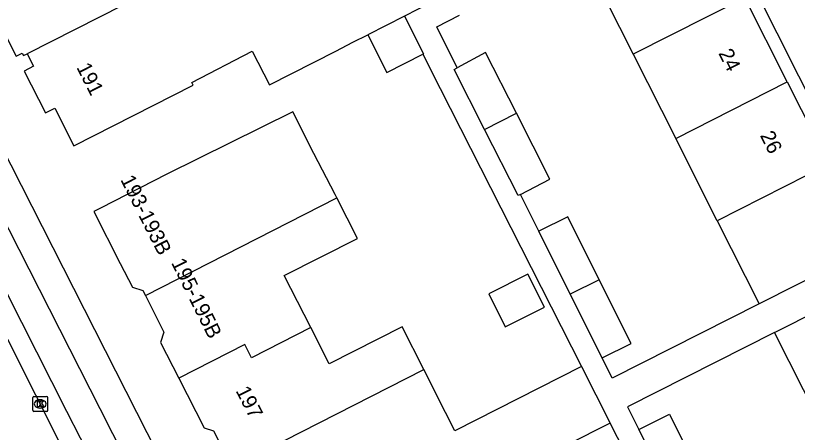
# Model space of a CAD drawing. Extents: x 162347 to 162868, y 381221 to 381813.
# Drawn here: x 162397.4 to 162450, y 381573.3 to 381601.3 of the extents above; entities that cross this region are included whole.
import ezdxf

# ---------------------------------------------------------------- set-up
doc = ezdxf.new("R2010")
doc.units = 0
for name, color, linetype in [('IMGEO_Fietspad_open', 7, 'Continuous'), ('IMGEO_Kolk', 7, 'Continuous'), ('IMGEO_Pand', 7, 'Continuous'), ('IMGEO_Pand_nummerreeks', 7, 'Continuous'), ('IMGEO_Rijbaan_regionaal_gesloten', 7, 'Continuous'), ('IMGEO_Voetpad_open', 7, 'Continuous')]:
    doc.layers.add(name, color=color, linetype=linetype)

msp = doc.modelspace()

# ---------------------------------------------------------------- linework, layer by layer
at = {"layer": 'IMGEO_Fietspad_open'}
for points in [[(162362.948, 381654.184), (162366.42, 381647.346), (162373.547, 381633.19), (162382.229, 381616.136), (162390.519, 381599.747), (162395.607, 381589.625), (162403.109, 381574.937), (162411.637, 381558.14), (162419.849, 381541.928), (162427.81, 381526.456), (162437.491, 381507.399), (162441.265, 381500), (162456.812, 381469.521), (162464.953, 381453.521)], [(162410.306, 381556.355), (162407.33, 381562.188), (162400.899, 381574.731), (162395.837, 381584.693), (162393.201, 381589.881), (162392.517, 381591.227), (162388.339, 381599.637), (162387.808, 381600.705), (162382.464, 381611.316), (162380.864, 381614.494), (162379.579, 381616.989), (162374.942, 381625.996), (162370.754, 381634.243), (162367.724, 381640.204), (162364.002, 381647.524), (162361.111, 381653.216)]]:
    msp.add_lwpolyline(points, dxfattribs=at)
at = {"layer": 'IMGEO_Kolk'}
for p, q in [((162398.602, 381574.808), (162398.602, 381575.66)), ((162398.677, 381575.734), (162399.529, 381575.734)), ((162399.09, 381575.514), (162399.115, 381575.514)), ((162399.603, 381575.66), (162399.603, 381574.808)), ((162399.113, 381574.954), (162399.088, 381574.954)), ((162399.529, 381574.734), (162398.677, 381574.734))]:
    msp.add_line(p, q, dxfattribs=at)
for points in [[(162398.602, 381574.808), (162398.602, 381575.66)], [(162398.677, 381575.734), (162399.529, 381575.734)], [(162398.923, 381575.434), (162399.046, 381575.434), (162399.046, 381575.283), (162399.176, 381575.434), (162399.34, 381575.434), (162399.194, 381575.283), (162399.347, 381575.034), (162399.195, 381575.034), (162399.11, 381575.198), (162399.046, 381575.131), (162399.046, 381575.034), (162398.923, 381575.034), (162398.923, 381575.434)], [(162399.603, 381575.66), (162399.603, 381574.808)], [(162399.529, 381574.734), (162398.677, 381574.734)]]:
    msp.add_lwpolyline(points, dxfattribs=at)
for centre, start, end in [((162398.679, 381575.658), 91.552, 178.448), ((162398.679, 381575.658), 91.552, 178.448), ((162399.527, 381575.658), 1.552, 88.448), ((162399.527, 381575.658), 1.552, 88.448), ((162398.679, 381574.81), 181.552, 268.448), ((162398.679, 381574.81), 181.552, 268.448), ((162399.527, 381574.81), 271.552, 358.448), ((162399.527, 381574.81), 271.552, 358.448)]:
    msp.add_arc(centre, 0.0765, start, end, dxfattribs=at)
for centre, major_axis, ratio, start_param, end_param in [((162399.089, 381575.234), (-0.387, 0.002), 0.722429, 4.712389, 7.853982), ((162399.114, 381575.234), (-0.39, 0.002), 0.717154, 1.570796, 4.712389)]:
    msp.add_ellipse(centre, major_axis=major_axis, ratio=ratio, start_param=start_param, end_param=end_param, dxfattribs=at)
at = {"layer": 'IMGEO_Pand'}
for points in [[(162408.169, 381603.815), (162408.091, 381603.968), (162407.93, 381604.285), (162406.673, 381606.755), (162409.231, 381608.056), (162407.798, 381610.873), (162399.497, 381606.65), (162395.04, 381604.382), (162395.432, 381603.613), (162395.031, 381603.409), (162397.484, 381598.588), (162397.885, 381598.792), (162397.971, 381598.622), (162398.225, 381598.75)], [(162421.093, 381610.584), (162425.348, 381602.17), (162423.591, 381601.277)], [(162408.169, 381603.815), (162407.903, 381603.676), (162398.225, 381598.75)], [(162436.22, 381604.184), (162438.975, 381598.725)], [(162446.477, 381602.521), (162438.975, 381598.725)], [(162449.333, 381596.861), (162446.477, 381602.521)], [(162423.591, 381601.277), (162421.123, 381600.023)], [(162423.591, 381601.277), (162424.876, 381598.735), (162424.83, 381598.712)], [(162398.225, 381598.75), (162398.654, 381597.907), (162398.031, 381597.59), (162399.459, 381594.783), (162400.082, 381595.1), (162401.374, 381592.559), (162409.395, 381596.64), (162409.305, 381596.816), (162413.361, 381598.924), (162414.513, 381596.661), (162418.97, 381598.929), (162420.127, 381599.517), (162421.123, 381600.023)], [(162421.123, 381600.023), (162422.406, 381597.486), (162424.83, 381598.712)], [(162431.122, 381594.751), (162429.049, 381598.831), (162427.136, 381597.807)], [(162438.975, 381598.725), (162441.832, 381593.065)], [(162428.983, 381593.669), (162426.937, 381597.701), (162427.136, 381597.807)], [(162441.832, 381593.065), (162449.333, 381596.861)], [(162449.333, 381596.861), (162452.128, 381591.331)], [(162419.052, 381589.067), (162418.929, 381589.309), (162417.498, 381592.056), (162416.078, 381594.848), (162407.611, 381590.658), (162403.154, 381588.39), (162402.711, 381588.165), (162404.489, 381584.67), (162405.3, 381583.076), (162406, 381582.848), (162406.171, 381582.512)], [(162428.983, 381593.669), (162431.122, 381594.751)], [(162431.389, 381589.304), (162433.37, 381590.327), (162431.122, 381594.751)], [(162431.389, 381589.304), (162431.238, 381589.226), (162428.983, 381593.669)], [(162444.624, 381587.534), (162441.832, 381593.065)], [(162452.128, 381591.331), (162444.624, 381587.534)], [(162406.171, 381582.512), (162419.052, 381589.067)], [(162417.289, 381580.365), (162415.516, 381583.85), (162420.434, 381586.352), (162419.052, 381589.067)], [(162436.693, 381583.574), (162434.575, 381587.809), (162432.624, 381586.834)], [(162444.624, 381587.534), (162447.443, 381581.948)], [(162434.744, 381582.595), (162432.624, 381586.834)], [(162454.951, 381585.737), (162447.443, 381581.948)], [(162429.261, 381582.633), (162430.371, 381580.414), (162433.002, 381581.73), (162431.892, 381583.949), (162429.261, 381582.633)], [(162448.475, 381580.031), (162451.541, 381581.582), (162456.002, 381583.84)], [(162436.693, 381583.574), (162434.744, 381582.595)], [(162436.878, 381578.326), (162438.829, 381579.302), (162436.693, 381583.574)], [(162406.171, 381582.512), (162407.423, 381580.052), (162407.199, 381579.365), (162408.417, 381576.971)], [(162436.878, 381578.326), (162434.744, 381582.595)], [(162417.289, 381580.365), (162413.312, 381578.341), (162412.859, 381579.232), (162408.417, 381576.971)], [(162424.894, 381577.551), (162423.437, 381580.415), (162418.533, 381577.92), (162417.289, 381580.365)], [(162451.409, 381574.236), (162448.475, 381580.031)], [(162412, 381570.989), (162424.894, 381577.551)], [(162435.49, 381577.756), (162426.984, 381573.427), (162426.362, 381574.649), (162424.894, 381577.551)], [(162435.49, 381577.756), (162437.424, 381573.954)], [(162408.417, 381576.971), (162410.117, 381573.63), (162410.763, 381573.42), (162412, 381570.989)], [(162439.361, 381573.514), (162441.413, 381574.54), (162443.458, 381570.449)], [(162437.424, 381573.954), (162428.846, 381569.617)], [(162440.071, 381568.694), (162439.413, 381570.046), (162437.424, 381573.954)], [(162441.411, 381569.413), (162439.361, 381573.514)]]:
    msp.add_lwpolyline(points, dxfattribs=at)
at = {"layer": 'IMGEO_Rijbaan_regionaal_gesloten'}
msp.add_lwpolyline([(162409.049, 381555.709), (162408.71, 381556.396), (162406.049, 381561.587), (162402.557, 381568.4), (162396.915, 381579.56), (162394.619, 381584.098), (162391.996, 381589.28), (162387.783, 381597.606), (162387.066, 381599.034), (162383.842, 381605.454), (162381.2, 381610.636), (162378.309, 381616.304), (162376.144, 381620.551), (162370.915, 381630.775), (162369.471, 381633.629), (162367.291, 381637.935), (162362.48, 381647.434), (162360.733, 381651.139), (162358.654, 381655.431)], dxfattribs=at)
at = {"layer": 'IMGEO_Voetpad_open'}
for points in [[(162415.849, 381663.025), (162416.703, 381663.475), (162450.084, 381597.259), (162455.733, 381586.132)], [(162466.79, 381454.429), (162443.597, 381500), (162364.764, 381654.894)], [(162427.136, 381597.807), (162425.761, 381600.556), (162427.294, 381601.337)], [(162424.83, 381598.712), (162425.995, 381596.421), (162435.49, 381577.756)], [(162432.624, 381586.834), (162431.389, 381589.304)], [(162447.443, 381581.948), (162437.563, 381576.962), (162436.878, 381578.326)], [(162448.475, 381580.031), (162438.602, 381575.032), (162439.361, 381573.514)]]:
    msp.add_lwpolyline(points, dxfattribs=at)

# ---------------------------------------------------------------- texts
at = {"layer": 'IMGEO_Pand_nummerreeks'}
for s, rotation, p in [('24', 296.8429, (162444.684, 381598.784)), ('191', 296.9632, (162401.513, 381597.844)), ('26', 296.8429, (162447.478, 381593.263)), ('193-193B', 296.8977, (162404.473, 381590.302)), ('195-195B', 296.4192, (162407.887, 381584.723)), ('197', 296.9779, (162412.225, 381576.127))]:
    msp.add_text(s, height=1, rotation=rotation, dxfattribs=at).set_placement(p)

doc.saveas('drawing.dxf')
